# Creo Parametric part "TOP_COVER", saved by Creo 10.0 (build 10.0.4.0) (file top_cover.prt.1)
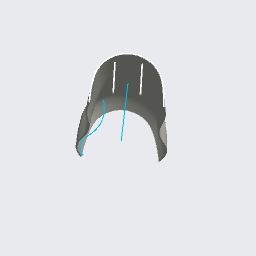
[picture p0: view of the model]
Units: millimeter Kilogram Sec (mmKs); MM, KILOGRAM, SECS

Created from: XX_SOLID_PART_MMKS_NEW_ABS.PRT

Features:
  1. datum plane "RIGHT"
  2. datum plane "TOP"
  3. datum plane "FRONT"
  4. coordinate system
  5. sketch "Sketch 1"
  6. datum plane "DTM1"
  7. datum plane "DTM2"
  8. datum plane "DTM4"
  9. datum plane "DTM3"
  10. revolve "Revolve 1"
  11. extrusion "Extrude 1"
  12. mirror "Mirror 1"
  13. datum plane "DTM5"
  14. sketch "Sketch 2"
  15. sketch "Sketch 3"
  16. sketch "Sketch 4"
  17. sketch "Sketch 5"
  18. sketch "Sketch 6"
  19. sketch "Sketch 7"
  20. mirror "Mirror 2"
  21. sketch "Sketch 7 (2)"
  22. sketch "Sketch 8"
  23. patch "Solidify 1"
  24. feature "Boundary Blend 1"
  25. protrusion "Thicken 1"
  26. extrusion "Extrude 2"

Other named items: RIGHT_1, TOP_1, FRONT_1, DTM1_1, DTM2_1, DTM3_1, DTM4_1, PRT_CSYS_DEF_2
